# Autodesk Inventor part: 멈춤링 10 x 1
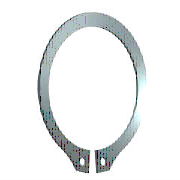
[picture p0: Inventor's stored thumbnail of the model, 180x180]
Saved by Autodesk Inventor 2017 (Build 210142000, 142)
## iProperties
IsCustomPart: 0
Created: 2021-07
Part Number: 멈춤링 10 x 1
Material: 강철, 연강
Description: 리테이닝 링(C형)
Document SubType Name: Modeling
Standard: KS B 1336
Designer: mdu
Standards Organization: KS
Language: ko-KR
Size Designation: 10 x 1
Categories: <MemberInstance><Categories><Category DisplayName="샤프트 부품" InternalName="7f7aeb1f-a693-4053-b835-cee3144e0d98" Mnemonic="SHFT"><Category DisplayName="써클립" Inter
Density: 7.86 g/cm^3
Mass: 0.423084 g
Surface Area: 1.9243 cm^2
Volume: 0.0538275 cm^3
Appearance: 파란색 - 벽 페인트 - 광택
Author: mdu
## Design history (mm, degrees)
sketch "스케치1"
  geometry: L1 (-6, 0)-(6, 0) reference; L2 (0, 20.189)-(0, -80.536) reference; L3 (-48.09, 0)-(48.09, 0) reference; L4 (-0.3, -9.791)-(-0.3, -12.791); L5 (-0.3, -6.54)-(-0.3, -13.29); L6 (-2.795, 1.6)-(3.672, 1.6); L7 (0.3, -6.54)-(0.3, -13.29); L8 (0.3, -9.791)-(0.3, -12.791); C1 r 0.6 at (-1.2, -11.486); C2 r 0.6 at (1.2, -11.486); A1 r 4.8 centre (0, -5) between (0.3, -9.791) and (-0.3, -9.791); A2 r 6.2 centre (0, -4.6) between (2.988, -10.033) and (-2.988, -10.033); A3 r 7.796 centre (0, -5) between (-1.418, -12.666) and (-0.3, -12.791); A4 r 1.2 centre (-1.2, -11.486) between (-2.383, -11.285) and (-1.418, -12.666); A5 r 1.2 centre (-3.566, -11.084) between (-2.383, -11.285) and (-2.988, -10.033); A6 r 1.2 centre (3.566, -11.084) between (2.988, -10.033) and (2.383, -11.285); A7 r 1.2 centre (1.2, -11.486) between (1.418, -12.666) and (2.383, -11.285); A8 r 7.796 centre (0, -5) between (0.3, -12.791) and (1.418, -12.666)
  constraints: 16 point on circle, 12 end point, 10 centre point, 9 symmetric about line, 5 point on line, 4 tangent, 3 coincident, 2 horizontal, 1 perpendicular, 1 vertical, 5 other
  dimensions: "d0" = 9.6 diameter of A1 (= ND); "d1" = 3 distance of L4.end L4.start (= SRB2); "d6" = 0.3 distance between parallel lines of L2 L5 (= 0.25 x SD5); "d7" = 1.6 distance between parallel lines of L6 L3 (= SRB1); "d8" = 0.4 distance of A1.centre A2.centre (= 0.25 x SRB1); "d9" = 1.2 radius of A4 (= SD5); "d10" = 1.2 radius of A5 (= SD5); "d11" = 0.9 distance from line of L4 A4.centre (= 0.75 x SD5); "d12" = 1.2 diameter of C1 (= SD5); "d13" = 1.2 diameter of C2 (= SD5); "d14" = 5 distance from line of A1.centre L1 (= 0.5 x WD)
extrude "본체" new body sketch "스케치1" distance "d2" = 1 (= SD); taper "d3" = 0 deg
workaxis "Work Axis1"
workplane "Work Plane1"
body "Solid1"
other parameters: "SD" = 1 [user parameter; used in 1 equation term], "SRB1" = 1.6 [user parameter; used in 2 equation terms], "ND" = 9.6 [user parameter; used in 1 equation term], "SRB2" = 3 [user parameter; used in 1 equation term], "SD5" = 1.2 [user parameter; used in 6 equation terms], "d15" = 0, "d16" = 0, "d17" = 0, "d41" = 0, "d42" = 0, "SD3" = 9.3 [user parameter], "WDMAX" = 11 [user parameter]
